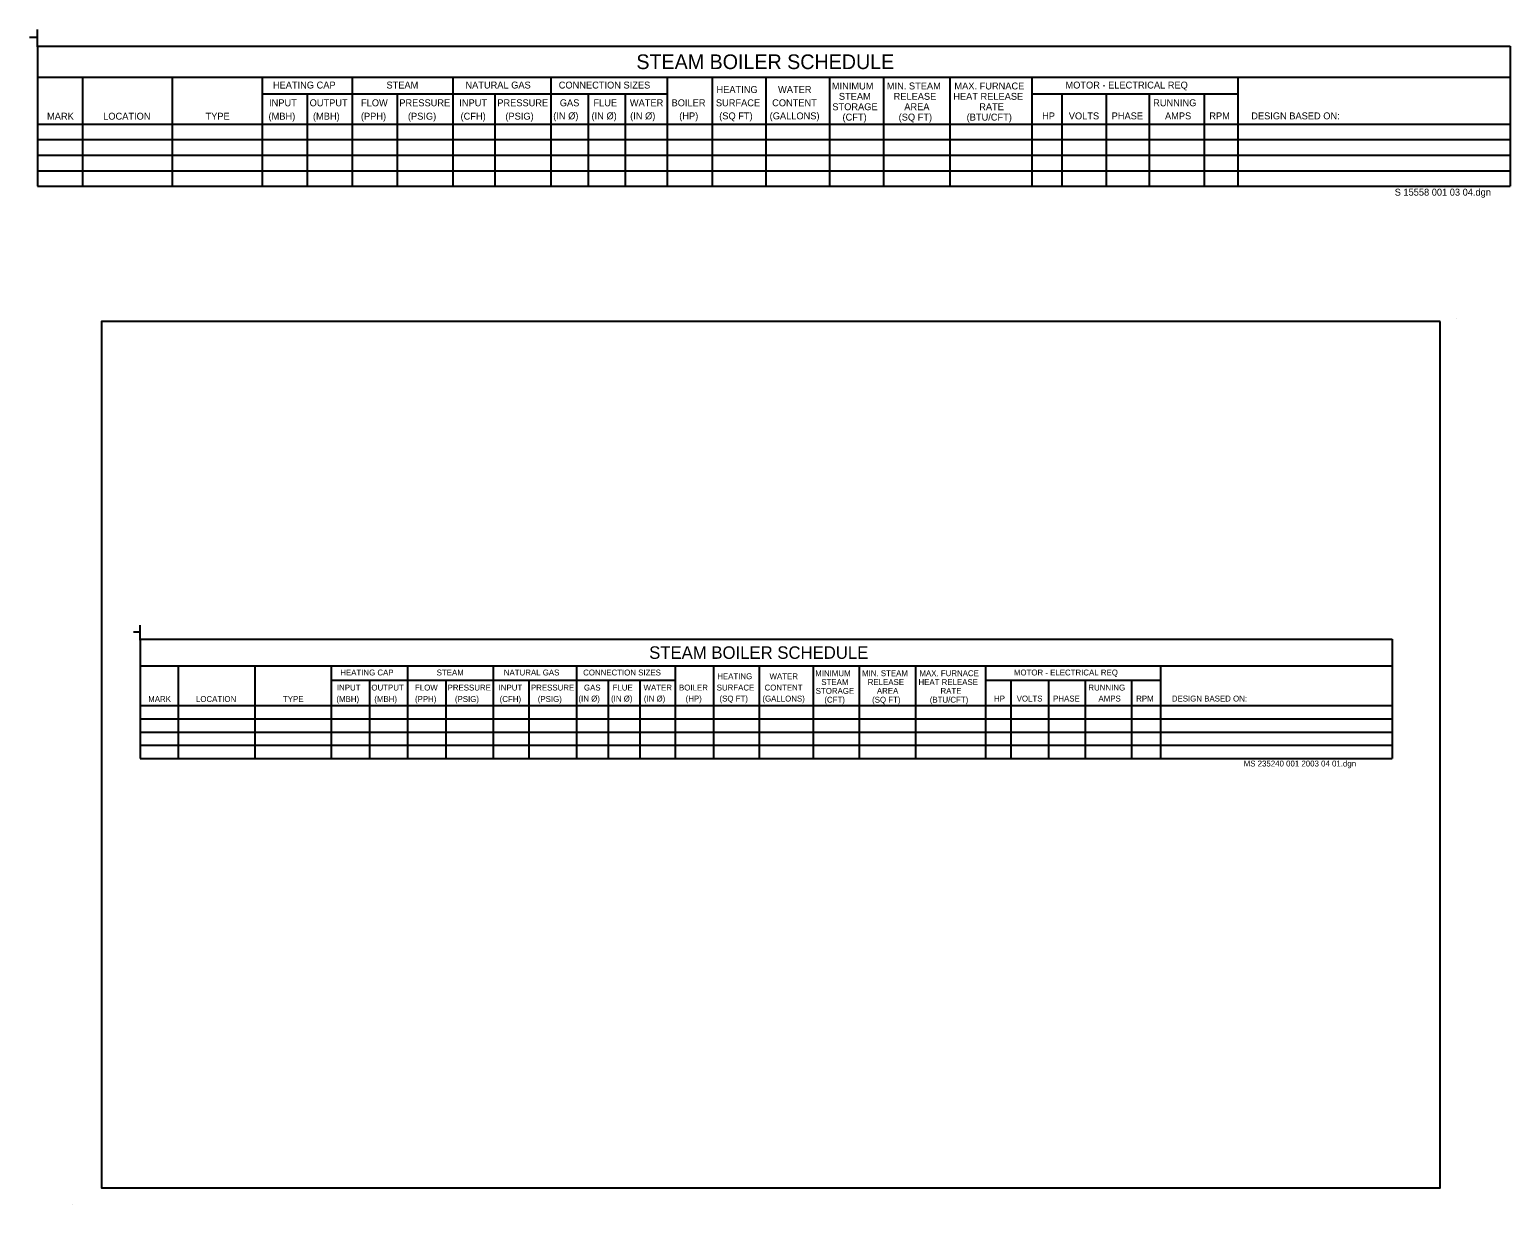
# Model space of a CAD drawing. Extents: x 10184 to 10326, y 10402 to 10515.
import ezdxf

# ---------------------------------------------------------------- set-up
doc = ezdxf.new("R2010")
doc.units = 0
for name, color, linetype in [('G-ANNO-PD', 7, 'Continuous'), ('G-ANNO-TEXT', 7, 'Continuous'), ('G-DETL-GRID', 7, 'Continuous'), ('G-SCHD-HTXT', 7, 'Continuous'), ('G-SCHD-LINE', 7, 'Continuous'), ('G-SCHD-TTXT', 7, 'Continuous')]:
    doc.layers.add(name, color=color, linetype=linetype)

msp = doc.modelspace()

# ---------------------------------------------------------------- linework, layer by layer
at = {"layer": 'G-ANNO-PD'}
for p, q in [((10321.17, 10487.43), (10321.17, 10487.43)), ((10187.81, 10402.07), (10187.81, 10402.07))]:
    msp.add_line(p, q, dxfattribs=at)
at = {"layer": 'G-DETL-GRID'}
msp.add_lwpolyline([(10319.57, 10487.12), (10190.59, 10487.12), (10190.59, 10403.65), (10319.57, 10403.65)], close=True, dxfattribs=at)
at = {"layer": 'G-SCHD-LINE'}
for p, q in [((10184.41, 10514.48), (10183.66, 10514.48)), ((10184.41, 10513.57), (10184.41, 10515.23)), ((10184.41, 10513.64), (10326.32, 10513.64)), ((10184.41, 10513.64), (10184.41, 10500.14)), ((10326.32, 10513.64), (10326.32, 10500.14)), ((10184.41, 10510.64), (10326.32, 10510.64)), ((10188.75, 10510.64), (10188.75, 10506.14)), ((10197.41, 10510.64), (10197.41, 10506.14)), ((10206.08, 10510.64), (10206.08, 10506.14)), ((10214.75, 10510.64), (10214.75, 10506.14)), ((10224.43, 10510.64), (10224.43, 10506.14)), ((10233.88, 10510.64), (10233.88, 10506.14)), ((10245.08, 10510.64), (10245.08, 10506.14)), ((10249.41, 10510.64), (10249.41, 10506.14)), ((10254.59, 10510.64), (10254.59, 10506.14)), ((10260.72, 10510.64), (10260.72, 10506.14)), ((10265.92, 10510.64), (10265.92, 10506.14)), ((10272.31, 10510.64), (10272.31, 10506.14)), ((10280.23, 10510.64), (10280.23, 10506.14)), ((10300.07, 10510.64), (10300.07, 10506.14)), ((10206.08, 10509.04), (10245.08, 10509.04)), ((10210.41, 10509.04), (10210.41, 10506.14)), ((10219.08, 10509.04), (10219.08, 10506.14)), ((10228.47, 10509.04), (10228.47, 10506.14)), ((10237.49, 10509.04), (10237.49, 10506.14)), ((10241.05, 10509.04), (10241.05, 10506.14)), ((10280.23, 10509.04), (10300.07, 10509.04)), ((10283.12, 10509.04), (10283.12, 10506.14)), ((10287.39, 10509.04), (10287.39, 10506.14)), ((10291.53, 10509.04), (10291.53, 10506.14)), ((10296.81, 10509.04), (10296.81, 10506.14)), ((10184.41, 10506.14), (10326.32, 10506.14)), ((10188.75, 10506.14), (10188.75, 10500.14)), ((10197.41, 10506.14), (10197.41, 10500.14)), ((10206.08, 10506.14), (10206.08, 10500.14)), ((10210.41, 10506.14), (10210.41, 10500.14)), ((10214.75, 10506.14), (10214.75, 10500.14)), ((10219.08, 10506.14), (10219.08, 10500.14)), ((10224.43, 10506.14), (10224.43, 10500.14)), ((10228.47, 10506.14), (10228.47, 10500.14)), ((10233.88, 10506.14), (10233.88, 10500.14)), ((10237.49, 10506.14), (10237.49, 10500.14)), ((10241.05, 10506.14), (10241.05, 10500.14)), ((10245.08, 10506.14), (10245.08, 10500.14)), ((10249.41, 10506.14), (10249.41, 10500.14)), ((10254.59, 10506.14), (10254.59, 10500.14)), ((10260.72, 10506.14), (10260.72, 10500.14)), ((10265.92, 10506.14), (10265.92, 10500.14)), ((10272.31, 10506.14), (10272.31, 10500.14)), ((10280.23, 10506.14), (10280.23, 10500.14)), ((10283.12, 10506.14), (10283.12, 10500.14)), ((10287.39, 10506.14), (10287.39, 10500.14)), ((10291.53, 10506.14), (10291.53, 10500.14)), ((10296.81, 10506.14), (10296.81, 10500.14)), ((10300.07, 10506.14), (10300.07, 10500.14)), ((10184.41, 10504.64), (10326.32, 10504.64)), ((10184.41, 10503.14), (10326.32, 10503.14)), ((10184.41, 10501.64), (10326.32, 10501.64)), ((10184.41, 10500.14), (10326.32, 10500.14)), ((10194.3, 10457.2), (10193.66, 10457.2)), ((10194.3, 10456.43), (10194.3, 10457.85)), ((10194.3, 10456.5), (10314.92, 10456.5)), ((10194.3, 10456.5), (10194.3, 10445.02)), ((10314.92, 10456.5), (10314.92, 10445.02)), ((10194.3, 10453.95), (10314.92, 10453.95)), ((10197.98, 10453.95), (10197.98, 10450.12)), ((10205.35, 10453.95), (10205.35, 10450.12)), ((10212.71, 10453.95), (10212.71, 10450.12)), ((10220.08, 10453.95), (10220.08, 10450.12)), ((10228.31, 10453.95), (10228.31, 10450.12)), ((10236.35, 10453.95), (10236.35, 10450.12)), ((10245.86, 10453.95), (10245.86, 10450.12)), ((10249.55, 10453.95), (10249.55, 10450.12)), ((10253.95, 10453.95), (10253.95, 10450.12)), ((10259.16, 10453.95), (10259.16, 10450.12)), ((10263.58, 10453.95), (10263.58, 10450.12)), ((10269.01, 10453.95), (10269.01, 10450.12)), ((10275.74, 10453.95), (10275.74, 10450.12)), ((10292.6, 10453.95), (10292.6, 10450.12)), ((10212.71, 10452.58), (10245.86, 10452.58)), ((10216.4, 10452.58), (10216.4, 10450.12)), ((10223.76, 10452.58), (10223.76, 10450.12)), ((10231.75, 10452.58), (10231.75, 10450.12)), ((10239.41, 10452.58), (10239.41, 10450.12)), ((10242.44, 10452.58), (10242.44, 10450.12)), ((10275.74, 10452.58), (10292.6, 10452.58)), ((10278.2, 10452.58), (10278.2, 10450.12)), ((10281.83, 10452.58), (10281.83, 10450.12)), ((10285.35, 10452.58), (10285.35, 10450.12)), ((10289.83, 10452.58), (10289.83, 10450.12)), ((10194.3, 10450.12), (10314.92, 10450.12)), ((10197.98, 10450.12), (10197.98, 10445.02)), ((10205.35, 10450.12), (10205.35, 10445.02)), ((10212.71, 10450.12), (10212.71, 10445.02)), ((10216.4, 10450.12), (10216.4, 10445.02)), ((10220.08, 10450.12), (10220.08, 10445.02)), ((10223.76, 10450.12), (10223.76, 10445.02)), ((10228.31, 10450.12), (10228.31, 10445.02)), ((10231.75, 10450.12), (10231.75, 10445.02)), ((10236.35, 10450.12), (10236.35, 10445.02)), ((10239.41, 10450.12), (10239.41, 10445.02)), ((10242.44, 10450.12), (10242.44, 10445.02)), ((10245.86, 10450.12), (10245.86, 10445.02)), ((10249.55, 10450.12), (10249.55, 10445.02)), ((10253.95, 10450.12), (10253.95, 10445.02)), ((10259.16, 10450.12), (10259.16, 10445.02)), ((10263.58, 10450.12), (10263.58, 10445.02)), ((10269.01, 10450.12), (10269.01, 10445.02)), ((10275.74, 10450.12), (10275.74, 10445.02)), ((10278.2, 10450.12), (10278.2, 10445.02)), ((10281.83, 10450.12), (10281.83, 10445.02)), ((10285.35, 10450.12), (10285.35, 10445.02)), ((10289.83, 10450.12), (10289.83, 10445.02)), ((10292.6, 10450.12), (10292.6, 10445.02)), ((10194.3, 10448.85), (10314.92, 10448.85)), ((10194.3, 10447.57), (10314.92, 10447.57)), ((10194.3, 10446.3), (10314.92, 10446.3)), ((10194.3, 10445.02), (10314.92, 10445.02))]:
    msp.add_line(p, q, dxfattribs=at)

# ---------------------------------------------------------------- texts
at = {"layer": 'G-ANNO-TEXT'}
for s, height, p in [('S 15558 001 03 04.dgn', 0.6667, (10315.18, 10499.24)), ('MS 235240 001 2003 04 01.dgn', 0.5667, (10300.63, 10444.25))]:
    msp.add_text(s, height=height, dxfattribs=at).set_placement(p)
at = {"layer": 'G-SCHD-HTXT'}
for s, height, p in [('HEATING CAP', 0.6667, (10207.1, 10509.56)), ('STEAM', 0.667, (10218.04, 10509.56)), ('NATURAL GAS', 0.6667, (10225.65, 10509.56)), ('CONNECTION SIZES', 0.6667, (10234.64, 10509.56)), ('MINIMUM', 0.667, (10260.95, 10509.47)), ('MIN. STEAM', 0.667, (10266.25, 10509.47)), ('MAX. FURNACE', 0.6667, (10272.76, 10509.47)), ('MOTOR - ELECTRICAL REQ', 0.6667, (10283.46, 10509.56)), ('HEATING', 0.667, (10249.84, 10509.13)), ('WATER', 0.667, (10255.77, 10509.13)), ('STEAM', 0.667, (10261.63, 10508.47)), ('RELEASE ', 0.667, (10266.9, 10508.47)), ('HEAT RELEASE ', 0.6667, (10272.65, 10508.47)), ('MARK', 0.667, (10185.34, 10506.56)), ('LOCATION', 0.667, (10190.75, 10506.56)), ('TYPE', 0.667, (10200.61, 10506.56)), ('(MBH)', 0.667, (10206.68, 10506.56)), ('INPUT', 0.667, (10206.73, 10507.85)), ('OUTPUT', 0.667, (10210.64, 10507.85)), ('(MBH)', 0.667, (10210.96, 10506.56)), ('(PPH)', 0.667, (10215.58, 10506.56)), ('FLOW', 0.667, (10215.59, 10507.85)), ('PRESSURE', 0.667, (10219.28, 10507.85)), ('(PSIG)', 0.667, (10220.11, 10506.56)), ('INPUT', 0.667, (10225.06, 10507.85)), ('(CFH)', 0.667, (10225.18, 10506.56)), ('PRESSURE', 0.667, (10228.72, 10507.85)), ('(PSIG)', 0.667, (10229.5, 10506.56)), ('(IN Ø)', 0.667, (10234.11, 10506.59)), ('GAS', 0.667, (10234.74, 10507.85)), ('(IN Ø)', 0.667, (10237.8, 10506.59)), ('FLUE', 0.667, (10237.98, 10507.85)), ('WATER', 0.667, (10241.49, 10507.85)), ('(IN Ø)', 0.667, (10241.52, 10506.59)), ('BOILER', 0.667, (10245.51, 10507.85)), ('(HP)', 0.667, (10246.25, 10506.59)), ('SURFACE', 0.667, (10249.78, 10507.85)), ('(SQ FT)', 0.667, (10250.1, 10506.59)), ('(GALLONS)', 0.667, (10254.96, 10506.59)), ('CONTENT', 0.667, (10255.2, 10507.85)), ('STORAGE', 0.667, (10261, 10507.47)), ('(CFT)', 0.667, (10261.98, 10506.47)), ('(SQ FT)', 0.667, (10267.39, 10506.47)), ('AREA', 0.667, (10267.93, 10507.47)), ('(BTU/CFT)', 0.667, (10273.94, 10506.47)), ('RATE', 0.667, (10275.15, 10507.47)), ('HP', 0.667, (10281.21, 10506.59)), ('VOLTS', 0.667, (10283.78, 10506.59)), ('PHASE', 0.667, (10287.91, 10506.59)), ('RUNNING', 0.667, (10291.91, 10507.85)), ('AMPS', 0.667, (10293.05, 10506.59)), ('RPM', 0.667, (10297.32, 10506.59)), ('DESIGN BASED ON:', 0.6667, (10301.36, 10506.59)), ('HEATING CAP', 0.5667, (10213.59, 10453.02)), ('STEAM', 0.567, (10222.88, 10453.02)), ('NATURAL GAS', 0.5667, (10229.35, 10453.02)), ('CONNECTION SIZES', 0.5667, (10236.99, 10453.02)), ('HEATING', 0.567, (10249.91, 10452.66)), ('WATER', 0.567, (10254.95, 10452.66)), ('MINIMUM', 0.567, (10259.35, 10452.95)), ('MIN. STEAM', 0.567, (10263.86, 10452.95)), ('MAX. FURNACE', 0.5667, (10269.39, 10452.95)), ('MOTOR - ELECTRICAL REQ', 0.5667, (10278.49, 10453.02)), ('INPUT', 0.567, (10213.27, 10451.57)), ('OUTPUT', 0.567, (10216.59, 10451.57)), ('FLOW', 0.567, (10220.79, 10451.57)), ('PRESSURE', 0.567, (10223.93, 10451.57)), ('INPUT', 0.567, (10228.85, 10451.57)), ('PRESSURE', 0.567, (10231.96, 10451.57)), ('GAS', 0.567, (10237.07, 10451.57)), ('FLUE', 0.567, (10239.83, 10451.57)), ('WATER', 0.567, (10242.81, 10451.57)), ('BOILER', 0.567, (10246.23, 10451.57)), ('SURFACE', 0.567, (10249.86, 10451.57)), ('CONTENT', 0.567, (10254.47, 10451.57)), ('STORAGE', 0.567, (10259.4, 10451.25)), ('STEAM', 0.567, (10259.94, 10452.1)), ('RELEASE ', 0.567, (10264.41, 10452.1)), ('AREA', 0.567, (10265.29, 10451.25)), ('HEAT RELEASE ', 0.5667, (10269.3, 10452.1)), ('RATE', 0.567, (10271.42, 10451.25)), ('RUNNING', 0.567, (10285.67, 10451.57)), ('MARK', 0.567, (10195.09, 10450.47)), ('LOCATION', 0.567, (10199.69, 10450.47)), ('TYPE', 0.567, (10208.07, 10450.47)), ('(MBH)', 0.567, (10213.22, 10450.47)), ('(MBH)', 0.567, (10216.87, 10450.47)), ('(PPH)', 0.567, (10220.79, 10450.47)), ('(PSIG)', 0.567, (10224.64, 10450.47)), ('(CFH)', 0.567, (10228.95, 10450.47)), ('(PSIG)', 0.567, (10232.62, 10450.47)), ('(IN Ø)', 0.567, (10236.54, 10450.51)), ('(IN Ø)', 0.567, (10239.68, 10450.51)), ('(IN Ø)', 0.567, (10242.84, 10450.51)), ('(HP)', 0.567, (10246.86, 10450.51)), ('(SQ FT)', 0.567, (10250.13, 10450.51)), ('(GALLONS)', 0.567, (10254.26, 10450.51)), ('(CFT)', 0.567, (10260.23, 10450.4)), ('(SQ FT)', 0.567, (10264.83, 10450.4)), ('(BTU/CFT)', 0.567, (10270.39, 10450.4)), ('HP', 0.567, (10276.58, 10450.51)), ('VOLTS', 0.567, (10278.76, 10450.51)), ('PHASE', 0.567, (10282.27, 10450.51)), ('AMPS', 0.567, (10286.64, 10450.51)), ('RPM', 0.567, (10290.27, 10450.51)), ('DESIGN BASED ON:', 0.5667, (10293.71, 10450.51))]:
    msp.add_text(s, height=height, dxfattribs=at).set_placement(p)
at = {"layer": 'G-SCHD-TTXT'}
for height, p in [(1.4167, (10242.12, 10511.43)), (1.2042, (10243.35, 10454.62))]:
    msp.add_text('STEAM BOILER SCHEDULE', height=height, dxfattribs=at).set_placement(p)

doc.saveas('drawing.dxf')
